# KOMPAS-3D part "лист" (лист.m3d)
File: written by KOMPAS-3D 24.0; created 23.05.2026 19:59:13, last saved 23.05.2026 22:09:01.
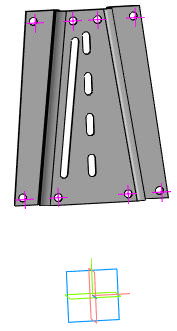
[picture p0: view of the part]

Document properties: Автор: R2D2; Полное имя файла: E:\Работа\Зайцев\GVKR1331E-1W-Fb-2P Задвижка шиберная DN.ru Ду50-300 Ру16-10-6\исходные материалы\DN80\лист.m3d

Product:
- Part/product: лист
    Масса: 0.899379
    Раздел спецификации: Прочие изделия
    Примечание: D040-08800

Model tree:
1. Эскиз:6  (with: Грань.Элемент выдавливания:15, Ребро.Элемент выдавливания:15)
2. Эскиз:7  (with: Грань.Элемент выдавливания:6, Ребро.Элемент выдавливания:6, Ребро.Элемент выдавливания:12)
3. Линейчатая обечайка:1
     Расстояние 1 = 10; Толщина листового тела = 4; Коэффициент = 0.5
4. Сгиб(1) - Линейчатая обечайка:1
     Радиус сгиба = 5; Коэффициент = 0.5; Величина сгиба = 5
5. Сгиб(2) - Линейчатая обечайка:1
     Радиус сгиба = 5; Коэффициент = 0.5; Величина сгиба = 5
6. Сгиб(3) - Линейчатая обечайка:1
     Радиус сгиба = 5; Коэффициент = 0.5; Величина сгиба = 5
7. Сгиб(4) - Линейчатая обечайка:1
     Радиус сгиба = 5; Коэффициент = 0.5; Величина сгиба = 5; Зазор = 1; Угол = 360; Параметр U, % = 100; Длина = 149
8. Эскиз:8  (with: Грань.Линейчатая обечайка:1, Ребро.Линейчатая обечайка:1)
9. Отверстие в листовом теле:1  (with: Грань.Линейчатая обечайка:1, Ребро.Линейчатая обечайка:1)
     Глубина выреза = 10; Диаметр отверстия = 8; Расстояние 1 = 7.5; Расстояние 2 = 7.5
10. Отверстие в листовом теле:2  (with: Грань.Линейчатая обечайка:1, Ребро.Линейчатая обечайка:1)
     Глубина выреза = 10; Диаметр отверстия = 8; Расстояние 1 = -7.5; Расстояние 2 = 7.5
11. Отверстие в листовом теле:3  (with: Грань.Линейчатая обечайка:1, Ребро.Линейчатая обечайка:1)
     Глубина выреза = 10; Диаметр отверстия = 8; Расстояние 1 = -76.0795; Расстояние 2 = 7.5
12. Отверстие в листовом теле:4  (with: Грань.Линейчатая обечайка:1, Ребро.Линейчатая обечайка:1)
     Глубина выреза = 10; Диаметр отверстия = 8; Расстояние 1 = -15.3275; Расстояние 2 = 7.5
13. Отверстие в листовом теле:5  (with: Грань.Линейчатая обечайка:1, Ребро.Линейчатая обечайка:1)
     Глубина выреза = 10; Диаметр отверстия = 8; Расстояние 1 = 7.5; Расстояние 2 = 181
14. Отверстие в листовом теле:6  (with: Грань.Линейчатая обечайка:1, Ребро.Линейчатая обечайка:1)
     Глубина выреза = 10; Диаметр отверстия = 8; Расстояние 1 = -7.5; Расстояние 2 = 181
15. Отверстие в листовом теле:7  (with: Грань.Линейчатая обечайка:1, Ребро.Линейчатая обечайка:1)
     Глубина выреза = 10; Диаметр отверстия = 8; Расстояние 1 = -31.673; Расстояние 2 = 181
16. Отверстие в листовом теле:8  (with: Грань.Линейчатая обечайка:1, Ребро.Линейчатая обечайка:1)
     Глубина выреза = 10; Диаметр отверстия = 8; Расстояние 1 = -19.5126; Расстояние 2 = 181
17. Эскиз:9  (with: Грань.Линейчатая обечайка:1, Ребро.Линейчатая обечайка:1)
18. Эскиз:10  (with: Грань.Линейчатая обечайка:1, Ребро.Линейчатая обечайка:1)
19. Вырез в листовом теле:1
     Глубина выреза = 10
20. Вырез в листовом теле:2
     Глубина выреза = 10
21. Массив по сетке:1  (with: Вырез в листовом теле:2, Эскиз:9, Эскиз:10)  (4 pattern instances)
     Угол раствора = 90; Геометрический массив = 128

Expressions: 4*h; 2*h; v1424-70
Referenced files in E:\Работа\Зайцев\GVKR1331E-1W-Fb-2P Задвижка шиберная DN.ru Ду50-300 Ру16-10-6\исходные материалы\DN80\: GVKR1331E-1W-Fb-2P Задвижка шиберная с выдвижным штоком DN.ru Ду80 Ру16.a3d
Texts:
  Затвор дисковый DN.ru Ду Ру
